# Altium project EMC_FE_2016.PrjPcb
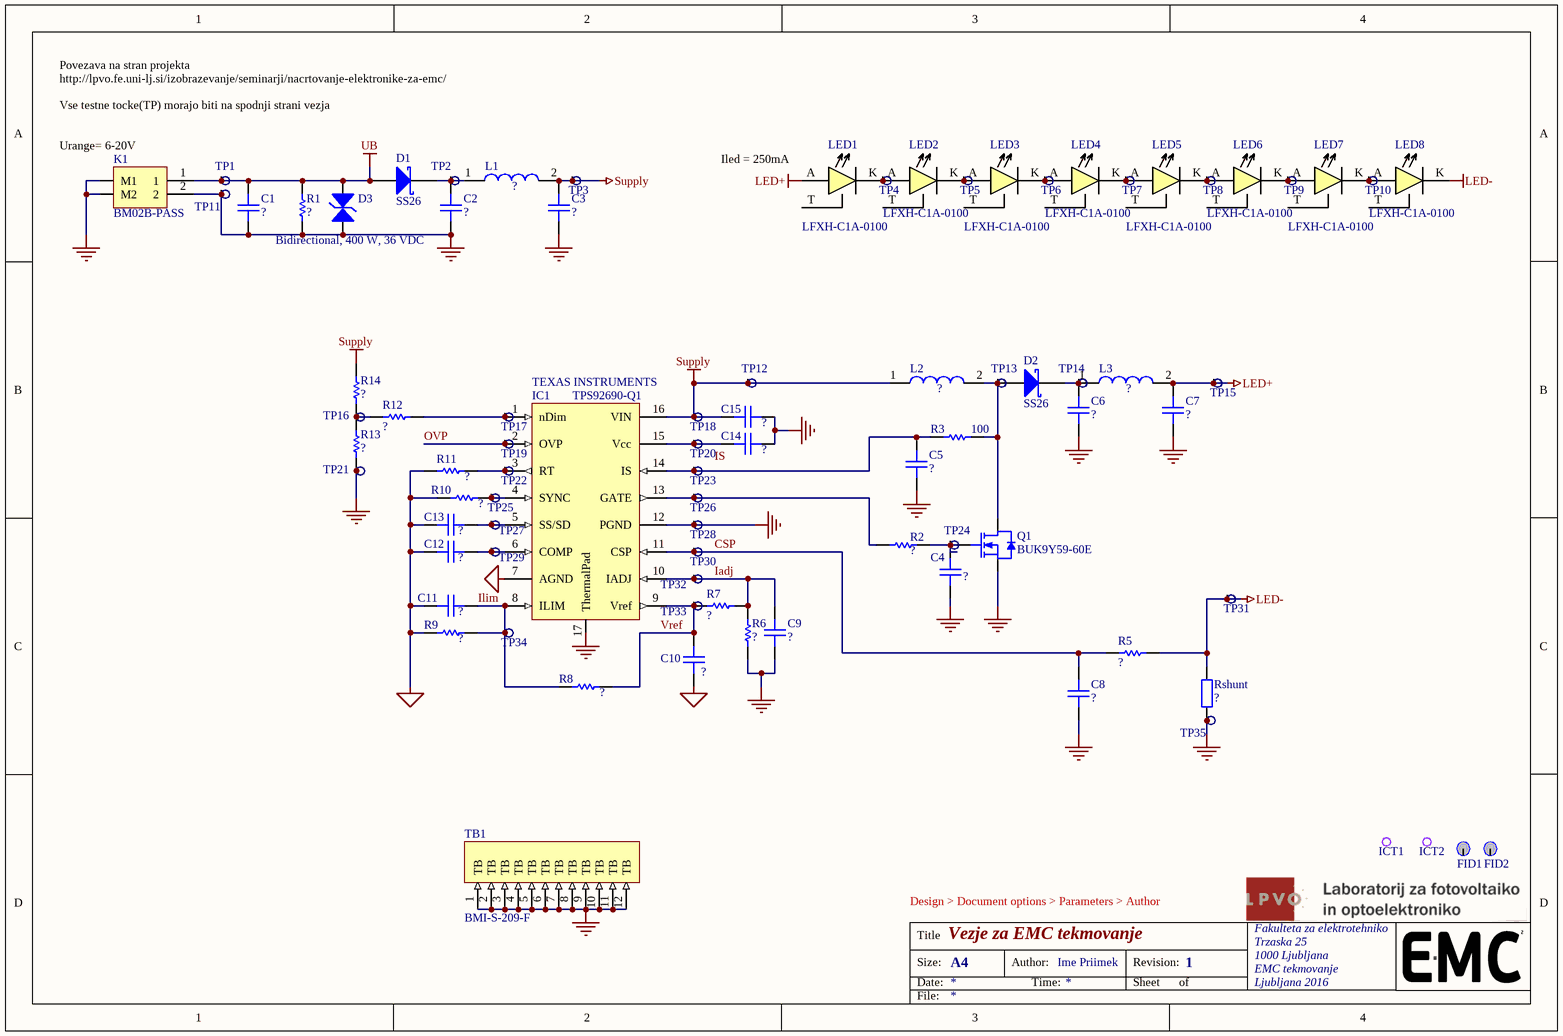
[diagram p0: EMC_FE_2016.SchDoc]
1 sheet, 86 parts. Net scope: global (net labels, ports and power ports of the same name join across sheets).
Board file: EMC_FE_2016.PcbDoc

## Sheet EMC_FE_2016.SchDoc: Vezje za EMC tekmovanje
size A4; Author: Ime Priimek; Organization: Fakulteta za elektrotehniko; Address1: Trzaska 25; Address2: 1000 Ljubljana; Address3: EMC tekmovanje; Address4: Ljubljana 2016; Revision: 1

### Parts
C1  ?  [C0805]
C2  ?  [C1210]
C3  ?  [C1210]
C4  ?  [C0603]
C5  ?  [C0603]
C6  ?  [C1206]
C7  ?  [C1206]
C8  ?  [C0603]
C9  ?  [C0603]
C10  ?  [C0603]
C11  ?  [C0603]
C12  ?  [C0603]
C13  ?  [C0603]
C14  ?  [C1206]
C15  ?  [C1210]
D1  SS26  [DO-214AA]
D2  SS26  [DO-214AA]
D3  Bidirectional, 400 W, 36 VDC  [DO-214AC_Bidirectional]
FID1  Fiducial  [Fiducial]  (value not drawn)
FID2  Fiducial  [Fiducial]  (value not drawn)
IC1  TPS92690-Q1  Manufacturer: TEXAS INSTRUMENTS  [MXA16A_L]
ICT1  ICT  [ICT_19]  (value not drawn)
ICT2  ICT  [ICT_19]  (value not drawn)
K1  BM02B-PASS  [BM02B-PASS]
L1  ?  [WE-PD2A_4532]
L2  ?  [WE-PD2A_4532]
L3  ?  [WE-PD2A_4532]
LED1  LFXH-C1A-0100  [LUXEON_F_CW]
LED2  LFXH-C1A-0100  [LUXEON_F_CW]
LED3  LFXH-C1A-0100  [LUXEON_F_CW]
LED4  LFXH-C1A-0100  [LUXEON_F_CW]
LED5  LFXH-C1A-0100  [LUXEON_F_CW]
LED6  LFXH-C1A-0100  [LUXEON_F_CW]
LED7  LFXH-C1A-0100  [LUXEON_F_CW]
LED8  LFXH-C1A-0100  [LUXEON_F_CW]
Q1  BUK9Y59-60E  [LFPAK56]
R1  ?  [R0805]
R2  ?  [R0603]
R3  100  [R0603]
R5  ?  [R0603]
R6  ?  [R0603]
R7  ?  [R0603]
R8  ?  [R0603]
R9  ?  [R0603]
R10  ?  [R0603]
R11  ?  [R0603]
R12  ?  [R0603]
R13  ?  [R0603]
R14  ?  [R0603]
Rshunt  ?  [R0805]
TB1  BMI-S-209-F  [BMI-S-209-F]
TP1  TP?  [Test_point_14]  (value not drawn)  (no BOM)
TP2  TP?  [Test_point_14]  (value not drawn)  (no BOM)
TP3  TP?  [Test_point_14]  (value not drawn)  (no BOM)
TP4  TP?  [Test_point_14]  (value not drawn)  (no BOM)
TP5  TP?  [Test_point_14]  (value not drawn)  (no BOM)
TP6  TP?  [Test_point_14]  (value not drawn)  (no BOM)
TP7  TP?  [Test_point_14]  (value not drawn)  (no BOM)
TP8  TP?  [Test_point_14]  (value not drawn)  (no BOM)
TP9  TP?  [Test_point_14]  (value not drawn)  (no BOM)
TP10  TP?  [Test_point_14]  (value not drawn)  (no BOM)
TP11  TP?  [Test_point_14]  (value not drawn)  (no BOM)
TP12  TP?  [Test_point_14]  (value not drawn)  (no BOM)
TP13  TP?  [Test_point_14]  (value not drawn)  (no BOM)
TP14  TP?  [Test_point_14]  (value not drawn)  (no BOM)
TP15  TP?  [Test_point_14]  (value not drawn)  (no BOM)
TP16  TP?  [Test_point_14]  (value not drawn)  (no BOM)
TP17  TP?  [Test_point_14]  (value not drawn)  (no BOM)
TP18  TP?  [Test_point_14]  (value not drawn)  (no BOM)
TP19  TP?  [Test_point_14]  (value not drawn)  (no BOM)
TP20  TP?  [Test_point_14]  (value not drawn)  (no BOM)
TP21  TP?  [Test_point_14]  (value not drawn)  (no BOM)
TP22  TP?  [Test_point_14]  (value not drawn)  (no BOM)
TP23  TP?  [Test_point_14]  (value not drawn)  (no BOM)
TP24  TP?  [Test_point_14]  (value not drawn)  (no BOM)
TP25  TP?  [Test_point_14]  (value not drawn)  (no BOM)
TP26  TP?  [Test_point_14]  (value not drawn)  (no BOM)
TP27  TP?  [Test_point_14]  (value not drawn)  (no BOM)
TP28  TP?  [Test_point_14]  (value not drawn)  (no BOM)
TP29  TP?  [Test_point_14]  (value not drawn)  (no BOM)
TP30  TP?  [Test_point_14]  (value not drawn)  (no BOM)
TP31  TP?  [Test_point_14]  (value not drawn)  (no BOM)
TP32  TP?  [Test_point_14]  (value not drawn)  (no BOM)
TP33  TP?  [Test_point_14]  (value not drawn)  (no BOM)
TP34  TP?  [Test_point_14]  (value not drawn)  (no BOM)
TP35  TP?  [Test_point_14]  (value not drawn)  (no BOM)

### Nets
GND: C1.1 C2.1 C3.1 C4.1 C5.2 C6.1 C7.1 C8.2 C9.1 C10.2 C11.1 C12.1 C13.1 C14.2 C15.1 D3.2 IC1.7(AGND) IC1.12(PGND) IC1.17(ThermalPad) K1.2 K1.M1 K1.M2 Q1.S R1.1 R6.1 R9.2 R10.2 R11.2 R13.1 Rshunt.1 TB1.1(TB) TB1.2(TB) TB1.3(TB) TB1.4(TB) TB1.5(TB) TB1.6(TB) TB1.7(TB) TB1.8(TB) TB1.9(TB) TB1.10(TB) TB1.11(TB) TB1.12(TB) TP11.T TP21.T TP28.T TP35.T
LED+: C7.2 L3.2 LED1.A TP15.T
LED-: LED8.K R5.1 Rshunt.2 TP31.T
Supply: C3.2 C15.2 IC1.16(VIN) L1.2 L2.1 R14.1 TP3.T TP12.T TP18.T
UB: C1.2 D1.A D3.1 K1.1 R1.2 TP1.T
CSP: C8.1 IC1.11(CSP) R5.2 TP30.T
Iadj: C9.2 IC1.10(IADJ) R6.2 R7.2 TP32.T
Ilim: C11.2 IC1.8(ILIM) R8.1 R9.1 TP34.T
OVP: IC1.2(OVP) TP19.T
Vref: C10.1 IC1.9(Vref) R7.1 R8.2 TP33.T
NetC2_2: C2.2 D1.K L1.1 TP2.T
NetC4_2: C4.2 Q1.G R2.1 TP24.T
NetC5_1: C5.1 IC1.14(IS) R3.2 TP23.T
NetC6_2: C6.2 D2.K L3.1 TP14.T
NetC12_2: C12.2 IC1.6(COMP) TP29.T
NetC13_2: C13.2 IC1.5(SS/SD) TP27.T
NetC14_1: C14.1 IC1.15(Vcc) TP20.T
NetD2_A: D2.A L2.2 Q1.D R3.1 TP13.T
NetIC1_1: IC1.1(nDim) R12.1 TP17.T
NetIC1_3: IC1.3(RT) R11.1 TP22.T
NetIC1_4: IC1.4(SYNC) R10.1 TP25.T
NetIC1_13: IC1.13(GATE) R2.2 TP26.T
NetLED1_K: LED1.K LED2.A TP4.T
NetLED2_K: LED2.K LED3.A TP5.T
NetLED3_K: LED3.K LED4.A TP6.T
NetLED4_K: LED4.K LED5.A TP7.T
NetLED5_K: LED5.K LED6.A TP8.T
NetLED6_K: LED6.K LED7.A TP9.T
NetLED7_K: LED7.K LED8.A TP10.T
NetR12_2: R12.2 R13.2 R14.2 TP16.T

Not connected (* = marked no-connect by the designer): FID1 F; FID2 F; LED1 T; LED2 T; LED3 T; LED4 T; LED5 T; LED6 T; LED7 T; LED8 T

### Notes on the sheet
- http://lpvo.fe.uni-lj.si/izobrazevanje/seminarji/nacrtovanje-elektronike-za-emc/
- Povezava na stran projekta
- Vse testne tocke(TP) morajo biti na spodnji strani vezja
- (near K1) Urange= 6-20V
- (near LED1) Iled = 250mA
- Design > Document options > Parameters > Author
- Title
- Size:
- Date:
- A4
- Author:
- Time:
- Revision:
- Sheet
- of
- File:
- Labels drawn without touching a wire or pin: IS

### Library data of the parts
C1-C15 = C: Capacitor
D1 D2 = SS26: Schottky Diode 2A; Manufacturer: VISHAY; Manufacturer Part Number: SS26-E3/52T.; Diode Configuration: Single; Repetitive Reverse Voltage Vrrm Max: 60; Forward Current If(AV): 2; Diode Case Style: DO-214; Forward Voltage VF Max: 700; Forward Surge Current Ifsm Max: 75
D3 = WE-TVSP DO-214AC, 824501361: WE-TVSP Power TVS Diode, bidirectional, 400 W, 36 VDC; Manufacturer: Wurth Elektronik
FID1 FID2 = Fiducial: according to IPC-7351 - is a 1mm diameter round dot with 2mm solder mask opening
IC1 = TPS92690-Q1: N-Channel Controller for Dimmable LED Drives With Low-Side Current Sense; Device Topology: Boost, Cuk, Flyback, SEPIC; Output Current Max: 5A; Output Voltage: 75; Driver Case Style: TSSOP; No. of Pins: 16; Input Voltage Min: 4.5; Dimming Control Type: Analogue, PWM; Input Voltage: 4.5V to 75; LED Driver Application: Automotive, General Illumination
ICT1 ICT2 = ICT: Alignmnt holes for In Circuit Testing
K1 = BM02B-PASS: Wire-To-Board Connector, PA Series, Surface Mount, Header, 2, 2 mm, Tin Plated Contacts; Manufacturer: JST (JAPAN SOLDERLESS TERMINALS); Manufacturer Part Number: BM02B-PASS-1-TFT(LF)(SN); No. of Contacts: 2; No. of Rows: 1; Contact Termination: Surface Mount Vertical
L1-L3 = WE-PD2A 4532, 7847730: WE-PD2A SMD Power Inductor, Inductance = 1.0 ¦ĚH; Manufacturer: Wurth Elektronik
LED1-LED8 = LFXH-C1A-0100: high-power, 1.9mm x 2.3mm LED, Cool White; Manufacturer: LUMILEDS; Product Range: LUXEON F Series; CCT Typ: 5800K; Luminous Flux @ Test: 186; Forward Current @ Test: 350; Forward Current If Max: 700; Forward Voltage @ Test: 2.77; Viewing Angle: 118°; LED Mounting: SMD; No. of Pins: 3
Q1 = BUK9Y59-60E: N-MOS, 16.7A, 60V, 0.044 ohm, 10V, 1.7V; Manufacturer: NXP; Transistor Polarity: N Channel; Continuous Drain Current Id: 16.7; Drain Source Voltage Vds: 60; On Resistance Rds(on): 0.044; Rds(on) Test Voltage Vgs: 10; Threshold Voltage Vgs: 1.7; Power Dissipation Pd: 37; Transistor Case Style: SOT-669; No. of Pins: 4; SVHC: No SVHC (15-Jun-2015)
R1-R3 R5-R14 = R: Resistor
Rshunt = R_shunt: Resistor
TB1 = BMI-S-209-F: SURFACE MOUNT,  EMI SHIELD; Manufacturer: LAIRD TECHNOLOGIES
TP1-TP35 = Test_point: In-circuit test probe contact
